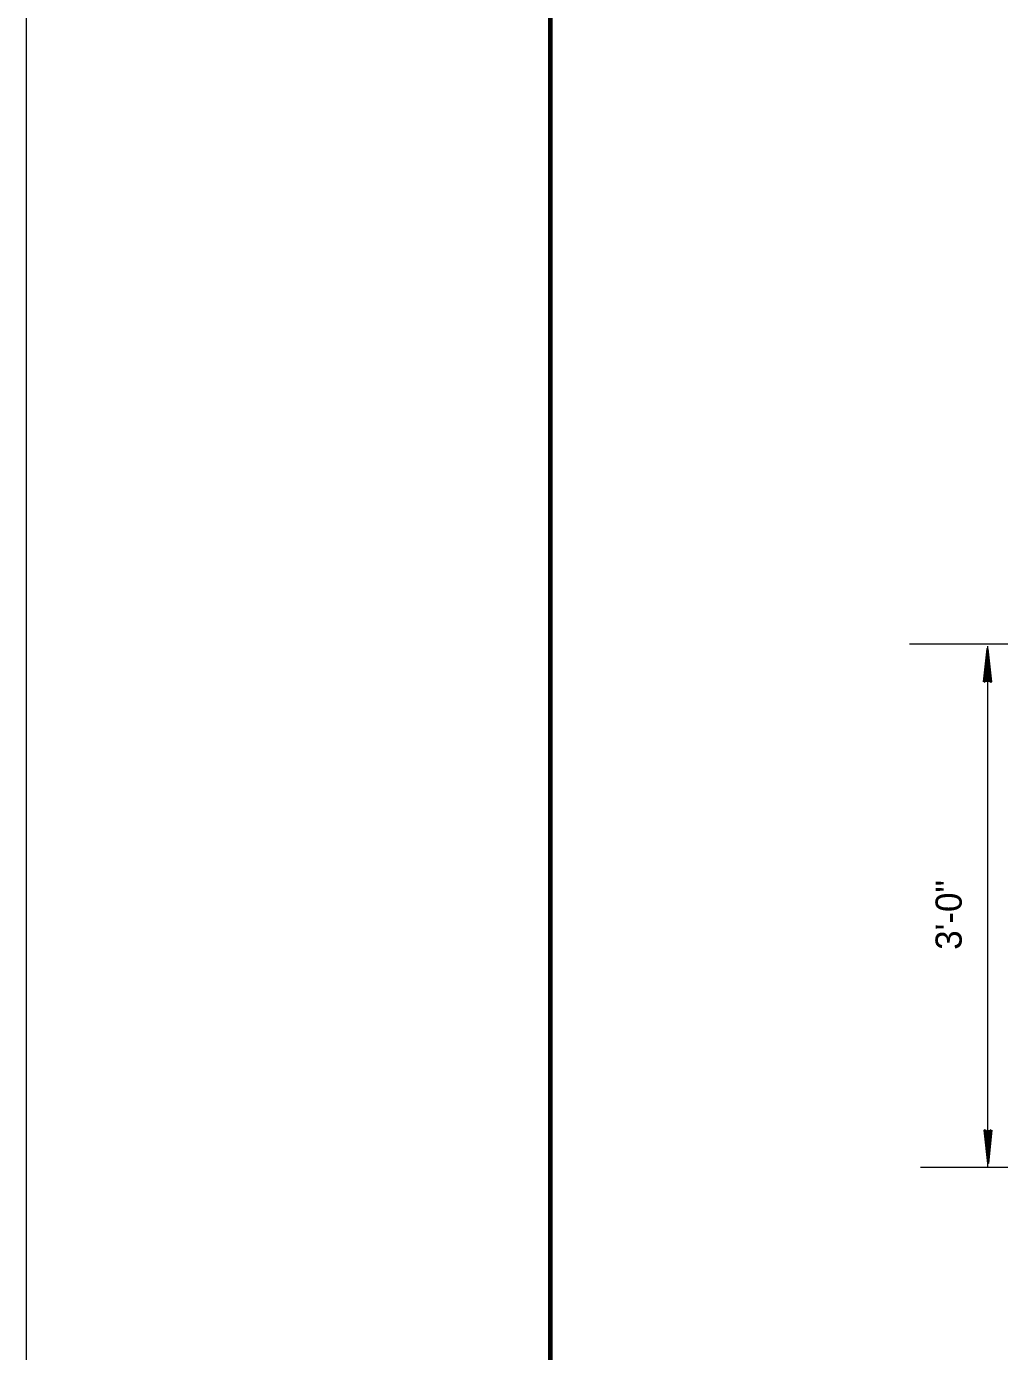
# Model space of a CAD drawing. Extents: x 14.14 to 17.34, y -1.61 to 0.38.
# Drawn here: x 14.1426 to 14.4524, y -0.6331 to -0.2114 of the extents above; entities that cross this region are included whole.
import ezdxf

# ---------------------------------------------------------------- set-up
doc = ezdxf.new("R2010")
doc.units = 0
doc.header["$LTSCALE"] = 0.0033
doc.layers.add('1', color=7, linetype='Continuous', lineweight=40)

msp = doc.modelspace()

# ---------------------------------------------------------------- linework, layer by layer
at = {"layer": '1', "lineweight": 13}
for p, q in [((14.142583, -1.605917), (14.142583, 0.382333)), ((14.423667, -0.407917), (14.5185, -0.407917)), ((14.4485, -0.408667), (14.4485, -0.574667)), ((14.42725, -0.574417), (14.568083, -0.574417))]:
    msp.add_line(p, q, dxfattribs=at)
at = {"layer": '1', "lineweight": 35}
for p, q in [((14.4475, -0.41975), (14.448417, -0.411917)), ((14.4475, -0.41975), (14.448417, -0.411917)), ((14.447583, -0.41975), (14.448417, -0.411917)), ((14.447667, -0.41975), (14.4485, -0.411917)), ((14.447667, -0.41975), (14.448667, -0.411917)), ((14.449167, -0.419833), (14.448417, -0.4125)), ((14.4485, -0.42), (14.4485, -0.409417)), ((14.449333, -0.41975), (14.4485, -0.412417)), ((14.449417, -0.41975), (14.448667, -0.412417)), ((14.449583, -0.41975), (14.44875, -0.412417)), ((14.447667, -0.562917), (14.4485, -0.57025)), ((14.447833, -0.562917), (14.448583, -0.57025)), ((14.447917, -0.562917), (14.44875, -0.57025)), ((14.448083, -0.562833), (14.448833, -0.570167)), ((14.449583, -0.562917), (14.448583, -0.57075)), ((14.44875, -0.562667), (14.44875, -0.57325)), ((14.449583, -0.562917), (14.44875, -0.57075)), ((14.44975, -0.562917), (14.448833, -0.57075)), ((14.44975, -0.562917), (14.448833, -0.57075)), ((14.449667, -0.562917), (14.448833, -0.57075))]:
    msp.add_line(p, q, dxfattribs=at)
at = {"layer": '1', "lineweight": 70}
msp.add_lwpolyline([(17.256, -1.521417), (17.256, 0.298667), (14.309333, 0.298667), (14.309333, -1.521417)], dxfattribs=at)
at = {"layer": '1', "lineweight": 35}
for points in [[(14.447417, -0.42), (14.4485, -0.409417), (14.449667, -0.42), (14.4485, -0.419417)], [(14.448417, -0.41925), (14.448333, -0.414583), (14.448417, -0.414583), (14.448417, -0.4155), (14.448333, -0.41925), (14.44825, -0.41625), (14.448167, -0.419417), (14.448083, -0.417167), (14.448, -0.419417), (14.44825, -0.415917), (14.448417, -0.41125), (14.448667, -0.412167), (14.448667, -0.410917), (14.448667, -0.41925), (14.448833, -0.416833), (14.448833, -0.419417), (14.448417, -0.414083), (14.449083, -0.419417)], [(14.449833, -0.562667), (14.44875, -0.57325), (14.447583, -0.562667), (14.44875, -0.56325)], [(14.448833, -0.563417), (14.448917, -0.568083), (14.448833, -0.568083), (14.448833, -0.567167), (14.448917, -0.563417), (14.449, -0.566417), (14.449083, -0.56325), (14.449167, -0.5655), (14.44925, -0.56325), (14.449, -0.56675), (14.448833, -0.571417), (14.448583, -0.5705), (14.448583, -0.57175), (14.448583, -0.563417), (14.448417, -0.565833), (14.448417, -0.56325), (14.448833, -0.568583), (14.448167, -0.56325)]]:
    msp.add_lwpolyline(points, close=True, dxfattribs=at)
for points in [[(14.448417, -0.41925), (14.447667, -0.419667), (14.447917, -0.419417), (14.44825, -0.41925), (14.448167, -0.419), (14.447833, -0.419167), (14.448583, -0.419333), (14.449083, -0.4195), (14.4495, -0.41975)], [(14.448833, -0.563417), (14.449583, -0.563), (14.449333, -0.56325), (14.449, -0.563417), (14.449083, -0.563667), (14.449417, -0.5635), (14.448667, -0.563333), (14.448167, -0.563167), (14.44775, -0.562917)]]:
    msp.add_lwpolyline(points, dxfattribs=at)

# ---------------------------------------------------------------- texts
at = {"layer": '1'}
msp.add_text('3\'-0"', height=0.008333, rotation=90, dxfattribs=at).set_placement((14.440333, -0.50525))

doc.saveas('drawing.dxf')
